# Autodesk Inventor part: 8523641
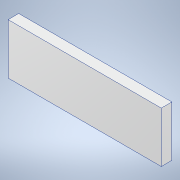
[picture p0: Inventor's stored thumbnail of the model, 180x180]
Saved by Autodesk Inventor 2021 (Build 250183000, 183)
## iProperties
Created: 2021-07
Part Number: 8523641
Material: Aluminum 6061
Document SubType Name: Sheet Metal
Designer: user
Density: 2.7 g/cm^3
Sheet Metal Rule: Default_mm
Appearance: Aluminum - Flat
Author: user
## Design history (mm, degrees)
sketch "Sketch1"
  geometry: 1 further point
node "Face1"
  sketch "Sketch2"
    geometry: L1 (0, 0)-(7.208, 0); L2 (7.208, 0)-(7.208, 2.381); L3 (7.208, 2.381)-(0, 2.381); L4 (0, 2.381)-(0, 0)
    constraints: 8 end point, 2 parallel, 1 horizontal, 1 perpendicular
body "Solid1"
face "Plate1" dims "d0" = 0.5 (= Thickness)
other parameters: "Thickness" = 0.5, "BendRadius" = 0.5 (= Thickness), "BendReliefWidth" = 0.5 (= Thickness), "BendReliefDepth" = 0.25 (= 0.5 x Thickness), "CornerReliefSize" = 2 (= 4 x Thickness), "SeamGap" = 0.01, "MinimumRemnant" = 1 (= 2 x Thickness), "TransitionRadius" = 0.5 (= BendRadius), "JacobiRadiusSize" = 0.5 (= BendRadius), "GapSize" = 0.5 (= Thickness)
